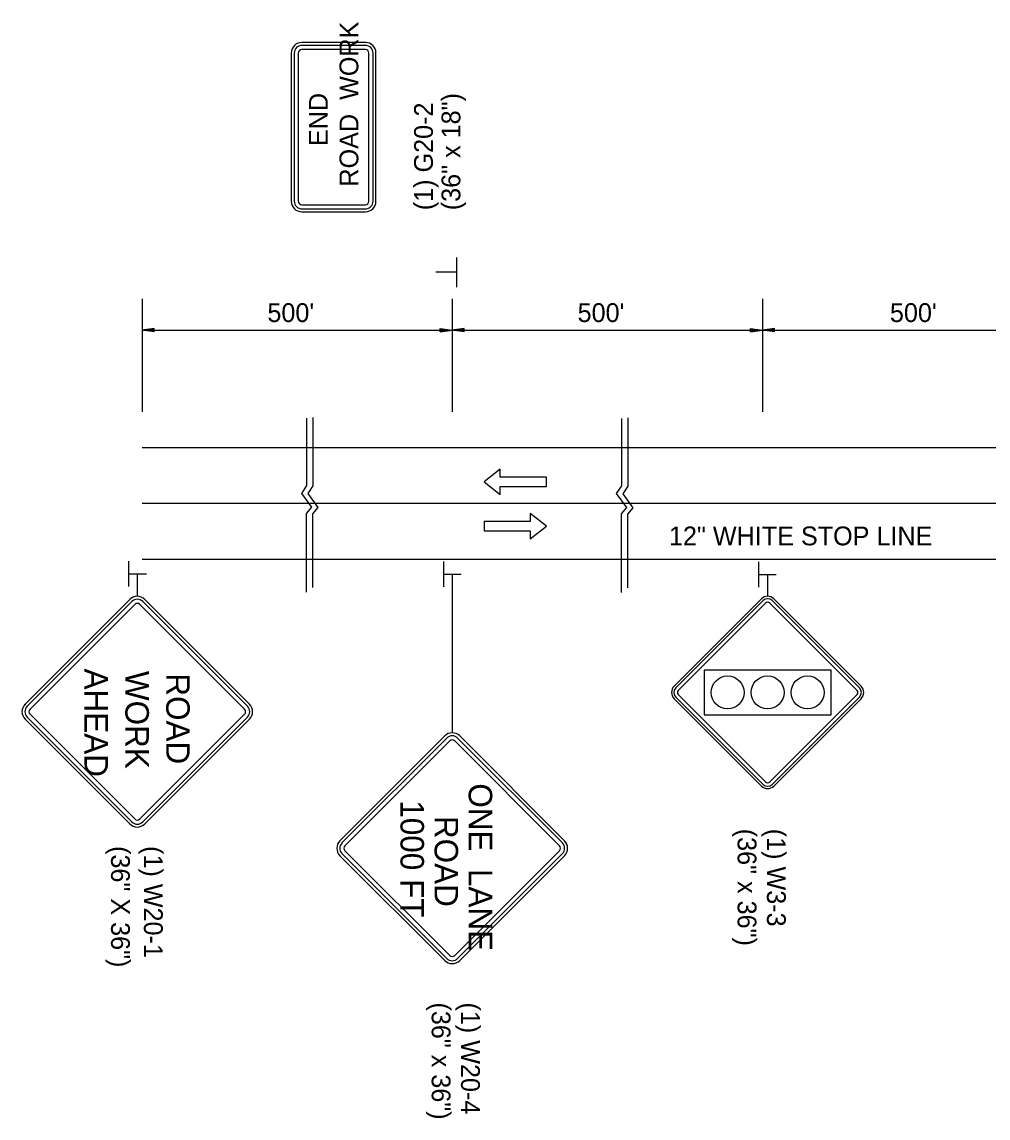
# Model space of a CAD drawing. Extents: x 1925873 to 1930787, y 596452 to 599617.
# Drawn here: x 1927912.8 to 1928220.8, y 597223.3 to 597572.8 of the extents above; entities that cross this region are included whole.
import ezdxf

# ---------------------------------------------------------------- set-up
doc = ezdxf.new("R2010")
doc.units = 0
for name, color, linetype in [('Default', 7, 'Continuous'), ('P_TC_Signs_Permanent', 7, 'Continuous'), ('P_TC_Signs_Temporary', 7, 'Continuous'), ('R_Border', 7, 'Continuous'), ('R_Striping', 7, 'Continuous')]:
    doc.layers.add(name, color=color, linetype=linetype)

msp = doc.modelspace()

# ---------------------------------------------------------------- linework, layer by layer
at = {"layer": 'Default'}
for p, q in [((1928051.3, 597497.69), (1928051.3, 597488.2)), ((1928051.16, 597492.97), (1928044.68, 597492.97)), ((1927951.04, 597484.55), (1927951.04, 597448.53)), ((1928049.94, 597484.55), (1928049.94, 597448.53)), ((1928148.84, 597484.55), (1928148.84, 597448.53)), ((1927954.87, 597475.09), (1927951.04, 597474.52)), ((1927951.04, 597474.52), (1928049.94, 597474.52)), ((1927954.87, 597473.94), (1927951.04, 597474.52)), ((1927954.87, 597475), (1927951.68, 597474.52)), ((1927954.87, 597474.04), (1927951.68, 597474.52)), ((1927954.87, 597474.9), (1927952.34, 597474.52)), ((1927954.87, 597474.13), (1927952.34, 597474.52)), ((1927954.87, 597474.8), (1927952.98, 597474.52)), ((1927954.87, 597474.23), (1927952.98, 597474.52)), ((1927954.87, 597474.7), (1927953.63, 597474.52)), ((1927954.87, 597474.33), (1927953.63, 597474.52)), ((1927954.87, 597474.61), (1927954.27, 597474.52)), ((1927954.87, 597474.43), (1927954.27, 597474.52)), ((1927954.87, 597473.94), (1927954.87, 597475.09)), ((1928046.1, 597475.09), (1928049.94, 597474.52)), ((1928046.1, 597473.94), (1928046.1, 597475.09)), ((1928046.1, 597475), (1928049.3, 597474.52)), ((1928046.1, 597474.9), (1928048.64, 597474.52)), ((1928046.1, 597474.8), (1928048, 597474.52)), ((1928046.1, 597474.7), (1928047.35, 597474.52)), ((1928046.1, 597474.61), (1928046.71, 597474.52)), ((1928046.1, 597473.94), (1928049.94, 597474.52)), ((1928046.1, 597474.33), (1928047.35, 597474.52)), ((1928046.1, 597474.13), (1928048.64, 597474.52)), ((1928046.1, 597474.04), (1928049.3, 597474.52)), ((1928046.1, 597474.23), (1928048, 597474.52)), ((1928046.1, 597474.43), (1928046.71, 597474.52)), ((1928053.77, 597475.09), (1928049.94, 597474.52)), ((1928049.94, 597474.52), (1928148.84, 597474.52)), ((1928053.77, 597473.94), (1928049.94, 597474.52)), ((1928053.77, 597475), (1928050.58, 597474.52)), ((1928053.77, 597474.04), (1928050.58, 597474.52)), ((1928053.77, 597474.9), (1928051.24, 597474.52)), ((1928053.77, 597474.13), (1928051.24, 597474.52)), ((1928053.77, 597474.8), (1928051.88, 597474.52)), ((1928053.77, 597474.23), (1928051.88, 597474.52)), ((1928053.77, 597474.7), (1928052.53, 597474.52)), ((1928053.77, 597474.33), (1928052.53, 597474.52)), ((1928053.77, 597474.61), (1928053.17, 597474.52)), ((1928053.77, 597474.43), (1928053.17, 597474.52)), ((1928053.77, 597473.94), (1928053.77, 597475.09)), ((1928145, 597475.09), (1928148.84, 597474.52)), ((1928145, 597473.94), (1928145, 597475.09)), ((1928145, 597475), (1928148.2, 597474.52)), ((1928145, 597474.9), (1928147.54, 597474.52)), ((1928145, 597474.8), (1928146.9, 597474.52)), ((1928145, 597474.7), (1928146.25, 597474.52)), ((1928145, 597474.61), (1928145.61, 597474.52)), ((1928145, 597473.94), (1928148.84, 597474.52)), ((1928145, 597474.33), (1928146.25, 597474.52)), ((1928145, 597474.13), (1928147.54, 597474.52)), ((1928145, 597474.04), (1928148.2, 597474.52)), ((1928145, 597474.23), (1928146.9, 597474.52)), ((1928145, 597474.43), (1928145.61, 597474.52)), ((1928152.67, 597475.09), (1928148.84, 597474.52)), ((1928148.84, 597474.52), (1928249.97, 597474.52)), ((1928152.67, 597473.94), (1928148.84, 597474.52)), ((1928152.67, 597475), (1928149.48, 597474.52)), ((1928152.67, 597474.04), (1928149.48, 597474.52)), ((1928152.67, 597474.9), (1928150.14, 597474.52)), ((1928152.67, 597474.13), (1928150.14, 597474.52)), ((1928152.67, 597474.8), (1928150.78, 597474.52)), ((1928152.67, 597474.23), (1928150.78, 597474.52)), ((1928152.67, 597474.7), (1928151.43, 597474.52)), ((1928152.67, 597474.33), (1928151.43, 597474.52)), ((1928152.67, 597474.61), (1928152.07, 597474.52)), ((1928152.67, 597474.43), (1928152.07, 597474.52)), ((1928152.67, 597473.94), (1928152.67, 597475.09)), ((1927951.04, 597437.1), (1928839.89, 597437.1)), ((1927951.04, 597419.31), (1928839.89, 597419.31)), ((1927946.86, 597392.82), (1927946.86, 597400.83)), ((1927951.04, 597401.52), (1928839.89, 597401.52)), ((1928047.26, 597392.72), (1928047.26, 597400.73)), ((1928147.66, 597392.62), (1928147.66, 597400.62)), ((1927946.98, 597396.8), (1927952.44, 597396.8)), ((1928047.38, 597396.7), (1928052.84, 597396.7)), ((1928147.78, 597396.6), (1928153.24, 597396.6))]:
    msp.add_line(p, q, dxfattribs=at)
for points in [[(1928003.51, 597446.49), (1928003.51, 597424.96), (1928001.85, 597422.49), (1928005.08, 597418.06), (1928003.38, 597416.02), (1928003.37, 597390.99)], [(1928005.55, 597446.68), (1928005.55, 597424.88), (1928003.89, 597422.41), (1928007.13, 597417.98), (1928005.42, 597415.93), (1928005.42, 597392.43)], [(1928103.91, 597446.39), (1928103.91, 597424.86), (1928102.25, 597422.39), (1928105.48, 597417.96), (1928103.78, 597415.92), (1928103.77, 597390.89)], [(1928105.95, 597446.58), (1928105.95, 597424.78), (1928104.29, 597422.31), (1928107.53, 597417.88), (1928105.82, 597415.83), (1928105.82, 597392.33)]]:
    msp.add_lwpolyline(points, dxfattribs=at)
at = {"layer": 'P_TC_Signs_Permanent'}
for p, q in [((1928120.68, 597360.99), (1928148.52, 597388.84)), ((1928121.21, 597360.46), (1928149.05, 597388.31)), ((1928149.85, 597387.51), (1928122, 597359.67)), ((1928179.02, 597359.67), (1928151.17, 597387.51)), ((1928151.97, 597388.31), (1928179.81, 597360.46)), ((1928152.5, 597388.84), (1928180.34, 597360.99)), ((1928122, 597358.34), (1928149.85, 597330.5)), ((1928151.17, 597330.5), (1928179.02, 597358.34)), ((1928148.52, 597329.17), (1928120.68, 597357.02)), ((1928149.05, 597329.71), (1928121.21, 597357.55)), ((1928179.81, 597357.55), (1928151.97, 597329.71)), ((1928180.34, 597357.02), (1928152.5, 597329.17))]:
    msp.add_line(p, q, dxfattribs=at)
msp.add_lwpolyline([(1928130.26, 597366.13), (1928130.26, 597351.88), (1928170.76, 597351.88), (1928170.76, 597366.13)], close=True, dxfattribs=at)
for centre in [(1928137.76, 597359.01), (1928150.51, 597359.01), (1928163.26, 597359.01)]:
    msp.add_circle(centre, 5.25, dxfattribs=at)
for centre, radius, start, end in [((1928150.51, 597386.85), 2.81, 45, 135), ((1928150.51, 597386.85), 2.06, 45, 135), ((1928150.51, 597386.85), 0.938, 45, 135), ((1928122.67, 597359.01), 2.81, 135, 225), ((1928122.67, 597359.01), 2.06, 135, 225), ((1928122.67, 597359.01), 0.938, 135, 225), ((1928178.35, 597359.01), 0.938, 315, 45), ((1928178.35, 597359.01), 2.06, 315, 45), ((1928178.35, 597359.01), 2.81, 315, 45), ((1928150.51, 597331.16), 0.938, 225, 315), ((1928150.51, 597331.16), 2.81, 225, 315), ((1928150.51, 597331.16), 2.06, 225, 315)]:
    msp.add_arc(centre, radius, start, end, dxfattribs=at)
at = {"layer": 'P_TC_Signs_Temporary'}
for p, q in [((1928022.26, 597566.25), (1928002.01, 597566.25)), ((1928022.26, 597565.31), (1928002.01, 597565.31)), ((1927998.63, 597562.87), (1927998.63, 597515.62)), ((1927999.57, 597562.87), (1927999.57, 597515.62)), ((1928000.88, 597562.87), (1928000.88, 597515.62)), ((1928022.26, 597564), (1928002.01, 597564)), ((1928023.38, 597515.62), (1928023.38, 597562.87)), ((1928024.7, 597515.62), (1928024.7, 597562.87)), ((1928025.63, 597515.62), (1928025.63, 597562.87)), ((1928002.01, 597514.5), (1928022.26, 597514.5)), ((1928002.01, 597513.19), (1928022.26, 597513.19)), ((1928002.01, 597512.25), (1928022.26, 597512.25)), ((1927913.74, 597355.26), (1927947.15, 597388.67)), ((1927914.4, 597354.6), (1927947.81, 597388.01)), ((1927915.33, 597353.67), (1927948.74, 597387.08)), ((1927950.33, 597387.08), (1927983.74, 597353.67)), ((1927951.26, 597388.01), (1927984.67, 597354.6)), ((1927951.92, 597388.67), (1927985.33, 597355.26)), ((1927947.81, 597317.74), (1927914.4, 597351.15)), ((1927948.74, 597318.67), (1927915.33, 597352.08)), ((1927983.74, 597352.08), (1927950.33, 597318.67)), ((1927984.67, 597351.15), (1927951.26, 597317.74)), ((1927947.15, 597317.08), (1927913.74, 597350.49)), ((1927985.33, 597350.49), (1927951.92, 597317.08)), ((1928014.14, 597311.72), (1928047.55, 597345.13)), ((1928014.8, 597311.06), (1928048.21, 597344.47)), ((1928051.66, 597344.47), (1928085.07, 597311.06)), ((1928052.32, 597345.13), (1928085.73, 597311.72)), ((1928015.73, 597310.13), (1928049.14, 597343.54)), ((1928050.73, 597343.54), (1928084.14, 597310.13)), ((1928047.55, 597273.54), (1928014.14, 597306.95)), ((1928048.21, 597274.2), (1928014.8, 597307.61)), ((1928049.14, 597275.13), (1928015.73, 597308.54)), ((1928084.14, 597308.54), (1928050.73, 597275.13)), ((1928085.07, 597307.61), (1928051.66, 597274.2)), ((1928085.73, 597306.95), (1928052.32, 597273.54))]:
    msp.add_line(p, q, dxfattribs=at)
for centre, radius, start, end in [((1928002.01, 597562.87), 3.37, 90, 180), ((1928002.01, 597562.87), 2.44, 90, 180), ((1928022.26, 597562.87), 3.37, 360, 90), ((1928022.26, 597562.87), 2.44, 360, 90), ((1928002.01, 597562.87), 1.13, 90, 180), ((1928022.26, 597562.87), 1.13, 360, 90), ((1928002.01, 597515.62), 3.37, 180, 270), ((1928002.01, 597515.62), 2.44, 180, 270), ((1928002.01, 597515.62), 1.13, 180, 270), ((1928022.26, 597515.62), 2.44, 270, 360), ((1928022.26, 597515.62), 1.13, 270, 360), ((1928022.26, 597515.62), 3.37, 270, 360), ((1927949.54, 597386.29), 3.37, 45, 135), ((1927949.54, 597386.29), 2.44, 45, 135), ((1927949.54, 597386.29), 1.12, 45, 135), ((1927916.13, 597352.88), 3.37, 135, 225), ((1927916.13, 597352.88), 2.44, 135, 225), ((1927982.95, 597352.88), 2.44, 315, 45), ((1927982.95, 597352.88), 3.37, 315, 45), ((1927916.13, 597352.88), 1.13, 135, 225), ((1927982.95, 597352.88), 1.13, 315, 45), ((1928049.94, 597342.75), 3.38, 45, 135), ((1928049.94, 597342.75), 2.44, 45, 135), ((1928049.94, 597342.75), 1.13, 45, 135), ((1927949.54, 597319.46), 3.37, 225, 315), ((1927949.54, 597319.46), 2.44, 225, 315), ((1927949.54, 597319.46), 1.12, 225, 315), ((1928016.53, 597309.34), 3.38, 135, 225), ((1928016.53, 597309.34), 2.44, 135, 225), ((1928016.53, 597309.34), 1.13, 135, 225), ((1928083.35, 597309.34), 1.13, 315, 45), ((1928083.35, 597309.34), 2.44, 315, 45), ((1928083.35, 597309.34), 3.38, 315, 45), ((1928049.94, 597275.93), 2.44, 225, 315), ((1928049.94, 597275.93), 1.13, 225, 315), ((1928049.94, 597275.93), 3.38, 225, 315)]:
    msp.add_arc(centre, radius, start, end, dxfattribs=at)
at = {"layer": 'R_Border'}
for p, q in [((1927949.54, 597396.8), (1927949.54, 597389.66)), ((1928049.94, 597396.7), (1928049.94, 597346.12)), ((1928150.51, 597396.6), (1928150.51, 597389.66))]:
    msp.add_line(p, q, dxfattribs=at)
at = {"layer": 'R_Striping'}
for points in [[(1928065.28, 597430.15), (1928060.09, 597426.15), (1928065.28, 597422.15), (1928065.28, 597424.65), (1928079.99, 597424.65), (1928079.99, 597427.65), (1928065.28, 597427.65)], [(1928074.8, 597408.02), (1928079.99, 597412.02), (1928074.8, 597416.02), (1928074.8, 597413.52), (1928060.09, 597413.52), (1928060.09, 597410.52), (1928074.8, 597410.52)]]:
    msp.add_lwpolyline(points, close=True, dxfattribs=at)

# ---------------------------------------------------------------- texts
at = {"layer": 'Default'}
for s, height, p in [("500'", 6, (1927991.02, 597477.11)), ("500'", 6, (1928089.92, 597477.11)), ("500'", 6, (1928189.5, 597477.11)), ('12" WHITE STOP LINE', 5.9996, (1928119.05, 597405.92))]:
    msp.add_text(s, height=height, rotation=360, dxfattribs=at).set_placement(p)
at = {"layer": 'P_TC_Signs_Temporary'}
for s, height, rotation, p in [('ROAD  WORK', 6, 90, (1928020.01, 597520.29)), ('END', 6, 90, (1928010.26, 597533.22)), (' AHEAD ', 7.5, 270, (1927932.7, 597369.42)), ('WORK', 7.5, 270, (1927945.73, 597365.87)), (' ROAD ', 7.5, 270, (1927958.75, 597367.9)), ('ONE  LANE', 7.5, 270, (1928055.19, 597330.04)), ('1000 FT', 7.5, 270, (1928033.44, 597324.63)), ('ROAD', 7.5, 270, (1928044.31, 597319.64))]:
    msp.add_text(s, height=height, rotation=rotation, dxfattribs=at).set_placement(p)
at = {"layer": 'R_Border'}
for s, height, rotation, p in [('(36" x 18")', 5.9996, 90, (1928052.54, 597512.76)), ('(1) G20-2', 6, 90, (1928043.79, 597512.76)), ('(36" x 36")', 5.9996, 270, (1928140.94, 597315.56)), ('(1) W3-3', 6, 270, (1928150.3, 597315.56)), ('(36" X 36")', 6, 270, (1927941.17, 597310.04)), ('(1) W20-1', 6, 270, (1927951.65, 597310.04)), ('(36" x 36")', 5.9996, 270, (1928043.4, 597260.17)), ('(1) W20-4', 6, 270, (1928052.76, 597260.17))]:
    msp.add_text(s, height=height, rotation=rotation, dxfattribs=at).set_placement(p)

doc.saveas('drawing.dxf')
